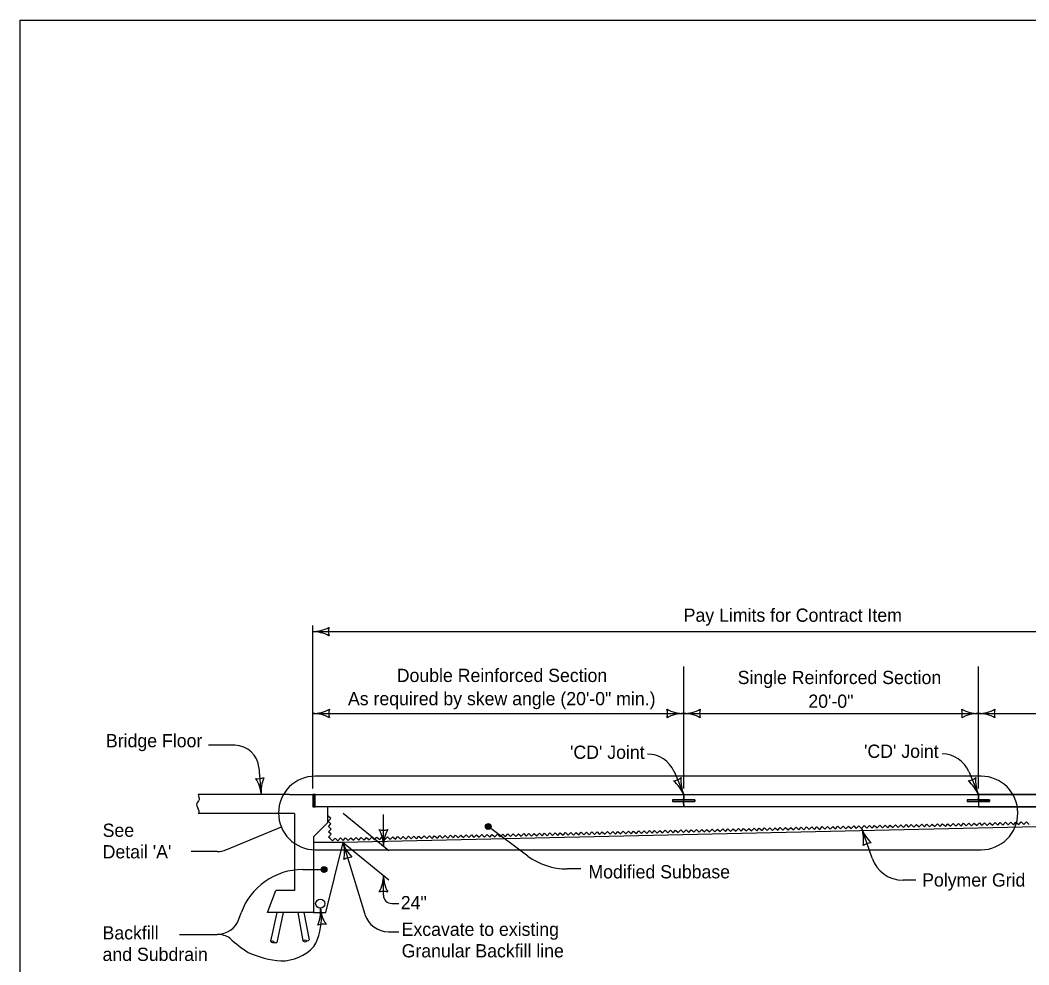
# Model space of a CAD drawing. Extents: x -2134934 to -2124557, y -2139046 to -2134021.
# Drawn here: x -2131334 to -2130115, y -2138178 to -2137036 of the extents above; entities that cross this region are included whole.
import ezdxf

# ---------------------------------------------------------------- set-up
doc = ezdxf.new("R2010")
doc.units = 0
for name, color, linetype in [('BridgeSuperStructureExisting', 7, 'Continuous'), ('dsnAlignmentStation', 7, 'Continuous'), ('dsnStdLabel', 7, 'Continuous')]:
    doc.layers.add(name, color=color, linetype=linetype)

msp = doc.modelspace()

# ---------------------------------------------------------------- linework, layer by layer
at = {"layer": 'BridgeSuperStructureExisting'}
for p, q in [((-2130980.5, -2137964.6), (-2130980.5, -2137767.6)), ((-2130980.5, -2137775), (-2129819.2, -2137775)), ((-2130532, -2137964.6), (-2130532, -2137817.1)), ((-2130175.6, -2137964.6), (-2130175.6, -2137817.1)), ((-2130980.5, -2137874), (-2130532, -2137874)), ((-2130532, -2137874), (-2130175.6, -2137874)), ((-2130175.6, -2137874), (-2129819.2, -2137874)), ((-2131074.8, -2137912.4), (-2131106.5, -2137912.4)), ((-2131045.7, -2137939.6), (-2131042.9, -2137972.1)), ((-2130172.4, -2137949.8), (-2130977.5, -2137949.8)), ((-2130543.6, -2137944.3), (-2130532, -2137972.1)), ((-2130187.2, -2137944.3), (-2130175.6, -2137972.1)), ((-2131008.7, -2137972.1), (-2131119.3, -2137972.1)), ((-2131008.7, -2137972.1), (-2130980.5, -2137972.1)), ((-2130980.5, -2137972.1), (-2130980.5, -2137986.9)), ((-2130977.5, -2137972.1), (-2130980.5, -2137972.1)), ((-2130980.5, -2137975.4), (-2130977.5, -2137972.5)), ((-2130980.5, -2137973.3), (-2130979.6, -2137972.5)), ((-2130977.5, -2137972.5), (-2130980.5, -2137972.5)), ((-2130980.5, -2137977.5), (-2130977.5, -2137974.6)), ((-2130980.5, -2137979.6), (-2130977.5, -2137976.7)), ((-2130980.5, -2137981.7), (-2130977.5, -2137978.8)), ((-2130977.5, -2137972.1), (-2129819.2, -2137972.1)), ((-2130545.4, -2137978.6), (-2130518.7, -2137978.6)), ((-2130545.4, -2137980.4), (-2130518.7, -2137980.4)), ((-2130545.4, -2137980.4), (-2130518.7, -2137980.4)), ((-2130532, -2137986.9), (-2130532, -2137972.1)), ((-2130518.7, -2137978.6), (-2130518.7, -2137980.4)), ((-2130189, -2137978.6), (-2130162.3, -2137978.6)), ((-2130189, -2137980.4), (-2130162.3, -2137980.4)), ((-2129819.2, -2137972.1), (-2130175.6, -2137972.1)), ((-2130175.6, -2137972.1), (-2130175.6, -2137978.6)), ((-2130175.6, -2137972.1), (-2130175.6, -2137986.9)), ((-2130175.6, -2137978.6), (-2130162.3, -2137978.6)), ((-2130162.3, -2137980.4), (-2130175.6, -2137980.4)), ((-2130175.6, -2137980.4), (-2130175.6, -2137986.9)), ((-2130162.3, -2137978.6), (-2130162.3, -2137980.4)), ((-2130162.3, -2137978.6), (-2130162.3, -2137980.4)), ((-2130980.5, -2137983.8), (-2130977.5, -2137980.9)), ((-2130980.5, -2137985.9), (-2130977.5, -2137983)), ((-2130980.5, -2137986.9), (-2130977.5, -2137986.9)), ((-2130979.3, -2137986.9), (-2130977.5, -2137985.1)), ((-2129819.2, -2137986.9), (-2130977.5, -2137986.9)), ((-2130962.7, -2137986.9), (-2130962.7, -2138006.2)), ((-2130175.6, -2137986.9), (-2129819.2, -2137986.9)), ((-2131002.8, -2137995), (-2131119.3, -2137995)), ((-2131002.8, -2137995), (-2131002.8, -2138087.9)), ((-2130943.9, -2137994.7), (-2130888.6, -2138039.7)), ((-2129819.2, -2138004.6), (-2130943.9, -2138030)), ((-2130895.1, -2138034.4), (-2130895.1, -2137996.2)), ((-2131018.7, -2138011.3), (-2131084.9, -2138038.7)), ((-2130962.7, -2138006.2), (-2130979.5, -2138023)), ((-2130720.3, -2138046.4), (-2130768.3, -2138010.8)), ((-2130304.1, -2138049), (-2130316.6, -2138013.1)), ((-2130979.5, -2138023), (-2130979.5, -2138114.6)), ((-2131096.2, -2138040.9), (-2131127.8, -2138040.9)), ((-2130943.9, -2138030), (-2130979.5, -2138030)), ((-2130977.5, -2138038.9), (-2130172.4, -2138038.9)), ((-2130964.6, -2138114.6), (-2130943.9, -2138030)), ((-2130943.9, -2138030), (-2130888.6, -2138075)), ((-2130917.4, -2138116.9), (-2130943.9, -2138030)), ((-2130656.2, -2138062), (-2130673.1, -2138062)), ((-2130895.1, -2138093.7), (-2130895.1, -2138069.7)), ((-2130251.3, -2138075.6), (-2130266.7, -2138075.6)), ((-2131035.4, -2138114.6), (-2131025.2, -2138087.9)), ((-2131002.8, -2138087.9), (-2131025.2, -2138087.9)), ((-2130979.5, -2138114.6), (-2131035.4, -2138114.6)), ((-2131024, -2138114.6), (-2131031.5, -2138149.4)), ((-2131016.4, -2138114.6), (-2131024.2, -2138151)), ((-2130998.7, -2138114.6), (-2130992.4, -2138149)), ((-2130991.2, -2138114.6), (-2130985.1, -2138147.6)), ((-2130979.5, -2138114.6), (-2130964.6, -2138114.6)), ((-2130885.1, -2138103.7), (-2130876.5, -2138103.7)), ((-2130889, -2138137.9), (-2130876.5, -2138137.9))]:
    msp.add_line(p, q, dxfattribs=at)
for points in [[(-2130959.7, -2138025), (-2130961.5, -2138023.4), (-2130958.4, -2138020.1), (-2130961.6, -2138017), (-2130958.5, -2138013.8), (-2130961.7, -2138010.7), (-2130958.7, -2138007.5), (-2130961.9, -2138004.4), (-2130958.8, -2138001.1), (-2130962, -2137998), (-2130961.9, -2137997.9)], [(-2130141.1, -2138007.2), (-2130139.5, -2138008.7), (-2130136.4, -2138005.5), (-2130133.2, -2138008.6), (-2130130.1, -2138005.3), (-2130126.8, -2138008.4), (-2130123.7, -2138005.2), (-2130120.5, -2138008.3), (-2130117.4, -2138005), (-2130114.2, -2138008.1)], [(-2130768, -2138007.6), (-2130769.2, -2138008.2), (-2130771, -2138008.7), (-2130771.3, -2138010.6), (-2130771.1, -2138012.2), (-2130769.9, -2138013.7), (-2130768.2, -2138013.5), (-2130766.4, -2138013.3), (-2130765.5, -2138011.8), (-2130765.3, -2138010.3), (-2130766.4, -2138008.3), (-2130767.7, -2138008.1), (-2130769.5, -2138008.6), (-2130771, -2138009.7), (-2130771, -2138011.5), (-2130769.8, -2138012.9), (-2130768.2, -2138013), (-2130766.4, -2138012.7), (-2130766.1, -2138011.6), (-2130765.7, -2138010.4), (-2130766.6, -2138008.9), (-2130767.9, -2138008.9), (-2130769.4, -2138009.2), (-2130770.5, -2138010), (-2130770, -2138011.5), (-2130768.8, -2138012.4), (-2130767.3, -2138012.5), (-2130766.9, -2138011.7), (-2130766.4, -2138010.7), (-2130767.2, -2138009.5), (-2130768.3, -2138009.2), (-2130769.3, -2138009.8), (-2130769.4, -2138010.9), (-2130768.8, -2138011.7), (-2130767.8, -2138012), (-2130767.3, -2138011.6), (-2130767, -2138010.9), (-2130767.6, -2138010), (-2130768.3, -2138009.9), (-2130769, -2138010.3), (-2130768.9, -2138010.9), (-2130768.4, -2138011.3), (-2130767.6, -2138011.3), (-2130767.7, -2138010.8), (-2130768.3, -2138010.5)], [(-2130673.2, -2138019.6), (-2130671.6, -2138021.2), (-2130668.5, -2138017.9), (-2130665.2, -2138021), (-2130662.2, -2138017.8), (-2130658.9, -2138020.9), (-2130655.8, -2138017.6), (-2130652.6, -2138020.7), (-2130649.5, -2138017.5), (-2130646.3, -2138020.6), (-2130643.2, -2138017.3), (-2130639.9, -2138020.4), (-2130636.8, -2138017.2), (-2130633.6, -2138020.3), (-2130630.5, -2138017), (-2130627.3, -2138020.1), (-2130624.2, -2138016.9), (-2130620.9, -2138020), (-2130617.8, -2138016.7), (-2130614.6, -2138019.8), (-2130611.5, -2138016.6), (-2130608.2, -2138019.7), (-2130605.1, -2138016.4), (-2130601.9, -2138019.5), (-2130598.8, -2138016.3), (-2130597.2, -2138017.8)], [(-2130597.2, -2138017.9), (-2130595.6, -2138019.4), (-2130592.5, -2138016.2), (-2130589.2, -2138019.3), (-2130586.1, -2138016), (-2130582.9, -2138019.1), (-2130579.8, -2138015.9), (-2130576.6, -2138019), (-2130573.5, -2138015.7), (-2130570.2, -2138018.8), (-2130567.1, -2138015.6), (-2130563.9, -2138018.7), (-2130560.8, -2138015.4), (-2130557.6, -2138018.5), (-2130554.5, -2138015.3), (-2130551.2, -2138018.4), (-2130548.1, -2138015.1), (-2130544.9, -2138018.2), (-2130541.8, -2138015), (-2130538.6, -2138018.1), (-2130535.5, -2138014.8), (-2130532.2, -2138017.9), (-2130529.1, -2138014.7), (-2130525.9, -2138017.8), (-2130522.8, -2138014.5), (-2130521.2, -2138016.1)], [(-2130521.2, -2138016.1), (-2130519.6, -2138017.6), (-2130516.5, -2138014.4), (-2130513.2, -2138017.4), (-2130510.1, -2138014.2), (-2130506.9, -2138017.3), (-2130503.8, -2138014.1), (-2130500.6, -2138017.2), (-2130497.5, -2138013.9), (-2130494.2, -2138017), (-2130491.1, -2138013.8), (-2130487.9, -2138016.9), (-2130484.8, -2138013.6), (-2130481.6, -2138016.7), (-2130478.5, -2138013.5), (-2130475.2, -2138016.6), (-2130472.1, -2138013.3), (-2130468.9, -2138016.4), (-2130465.8, -2138013.2), (-2130462.6, -2138016.3), (-2130459.5, -2138013), (-2130456.2, -2138016.1), (-2130453.1, -2138012.9), (-2130449.9, -2138016), (-2130446.8, -2138012.7), (-2130445.2, -2138014.3)], [(-2130445.2, -2138014.3), (-2130443.6, -2138015.8), (-2130440.5, -2138012.6), (-2130437.2, -2138015.7), (-2130434.1, -2138012.4), (-2130430.9, -2138015.5), (-2130427.8, -2138012.3), (-2130424.6, -2138015.4), (-2130421.5, -2138012.1), (-2130418.2, -2138015.2), (-2130415.1, -2138012), (-2130411.9, -2138015.1), (-2130408.8, -2138011.8), (-2130405.5, -2138014.9), (-2130402.5, -2138011.7), (-2130399.2, -2138014.8), (-2130396.1, -2138011.5), (-2130392.9, -2138014.6), (-2130389.8, -2138011.4), (-2130386.5, -2138014.5), (-2130383.5, -2138011.2), (-2130380.2, -2138014.3), (-2130377.1, -2138011.1), (-2130373.9, -2138014.2), (-2130370.8, -2138010.9), (-2130369.2, -2138012.5)], [(-2130369.2, -2138012.5), (-2130367.5, -2138014.1), (-2130364.4, -2138010.8), (-2130361.2, -2138013.9), (-2130358.1, -2138010.7), (-2130354.9, -2138013.8), (-2130351.8, -2138010.5), (-2130348.5, -2138013.6), (-2130345.4, -2138010.4), (-2130342.2, -2138013.5), (-2130339.1, -2138010.2), (-2130335.9, -2138013.3), (-2130332.8, -2138010.1), (-2130329.5, -2138013.2), (-2130326.4, -2138009.9), (-2130323.2, -2138013), (-2130320.1, -2138009.8), (-2130316.9, -2138012.9), (-2130313.8, -2138009.6), (-2130310.5, -2138012.7), (-2130307.4, -2138009.5), (-2130304.2, -2138012.6), (-2130301.1, -2138009.3), (-2130297.9, -2138012.4), (-2130294.8, -2138009.2), (-2130293.2, -2138010.7)], [(-2130293.2, -2138010.7), (-2130291.5, -2138012.3), (-2130288.4, -2138009), (-2130285.2, -2138012.1), (-2130282.1, -2138008.9), (-2130278.9, -2138012), (-2130275.8, -2138008.7), (-2130272.5, -2138011.8), (-2130269.4, -2138008.6), (-2130266.2, -2138011.7), (-2130263.1, -2138008.4), (-2130259.9, -2138011.5), (-2130256.8, -2138008.3), (-2130253.5, -2138011.4), (-2130250.4, -2138008.1), (-2130247.2, -2138011.2), (-2130244.1, -2138008), (-2130240.9, -2138011.1), (-2130237.8, -2138007.8), (-2130234.5, -2138010.9), (-2130231.4, -2138007.7), (-2130228.2, -2138010.8), (-2130225.1, -2138007.6), (-2130221.9, -2138010.7), (-2130218.8, -2138007.4), (-2130217.1, -2138009)], [(-2130217.1, -2138009), (-2130215.5, -2138010.5), (-2130212.4, -2138007.3), (-2130209.2, -2138010.4), (-2130206.1, -2138007.1), (-2130202.9, -2138010.2), (-2130199.8, -2138007), (-2130196.5, -2138010.1), (-2130193.4, -2138006.8), (-2130190.2, -2138009.9), (-2130187.1, -2138006.7), (-2130183.8, -2138009.8), (-2130180.8, -2138006.5), (-2130177.5, -2138009.6), (-2130174.4, -2138006.4), (-2130171.2, -2138009.5), (-2130168.1, -2138006.2), (-2130164.8, -2138009.3), (-2130161.8, -2138006.1), (-2130158.5, -2138009.2), (-2130155.4, -2138005.9), (-2130152.2, -2138009), (-2130149.1, -2138005.8), (-2130145.8, -2138008.9), (-2130142.8, -2138005.6), (-2130141.1, -2138007.2)], [(-2130959.9, -2138024.9), (-2130959.9, -2138024.8), (-2130956.6, -2138027.9), (-2130953.5, -2138024.7), (-2130950.3, -2138027.8), (-2130947.2, -2138024.5), (-2130944, -2138027.6), (-2130940.9, -2138024.4), (-2130937.6, -2138027.5), (-2130934.5, -2138024.2), (-2130931.3, -2138027.3), (-2130928.2, -2138024.1), (-2130925, -2138027.2), (-2130921.9, -2138023.9), (-2130918.6, -2138027), (-2130915.5, -2138023.8), (-2130912.3, -2138026.9), (-2130909.2, -2138023.6), (-2130906, -2138026.7), (-2130902.9, -2138023.5), (-2130901.2, -2138025)], [(-2130901.2, -2138025), (-2130899.6, -2138026.5), (-2130896.5, -2138023.3), (-2130893.3, -2138026.4), (-2130890.2, -2138023.1), (-2130886.9, -2138026.2), (-2130883.9, -2138023), (-2130880.6, -2138026.1), (-2130877.5, -2138022.8), (-2130874.3, -2138025.9), (-2130871.2, -2138022.7), (-2130867.9, -2138025.8), (-2130864.9, -2138022.5), (-2130861.6, -2138025.6), (-2130858.5, -2138022.4), (-2130855.3, -2138025.5), (-2130852.2, -2138022.2), (-2130848.9, -2138025.3), (-2130845.8, -2138022.1), (-2130842.6, -2138025.2), (-2130839.5, -2138021.9), (-2130836.3, -2138025), (-2130833.2, -2138021.8), (-2130829.9, -2138024.9), (-2130826.8, -2138021.6), (-2130825.2, -2138023.2)], [(-2130825.2, -2138023.2), (-2130823.6, -2138024.7), (-2130820.5, -2138021.5), (-2130817.3, -2138024.6), (-2130814.2, -2138021.3), (-2130810.9, -2138024.4), (-2130807.8, -2138021.2), (-2130804.6, -2138024.3), (-2130801.5, -2138021), (-2130798.3, -2138024.1), (-2130795.2, -2138020.9), (-2130791.9, -2138024), (-2130788.8, -2138020.7), (-2130785.6, -2138023.8), (-2130782.5, -2138020.6), (-2130779.3, -2138023.7), (-2130776.2, -2138020.5), (-2130772.9, -2138023.5), (-2130769.8, -2138020.3), (-2130766.6, -2138023.4), (-2130763.5, -2138020.2), (-2130760.3, -2138023.2), (-2130757.2, -2138020), (-2130753.9, -2138023.1), (-2130750.8, -2138019.9), (-2130749.2, -2138021.4)], [(-2130749.2, -2138021.4), (-2130747.6, -2138022.9), (-2130744.5, -2138019.7), (-2130741.3, -2138022.8), (-2130738.2, -2138019.6), (-2130734.9, -2138022.6), (-2130731.8, -2138019.4), (-2130728.6, -2138022.5), (-2130725.5, -2138019.3), (-2130722.3, -2138022.3), (-2130719.2, -2138019.1), (-2130715.9, -2138022.2), (-2130712.8, -2138019), (-2130709.6, -2138022.1), (-2130706.5, -2138018.8), (-2130703.3, -2138021.9), (-2130700.2, -2138018.7), (-2130696.9, -2138021.8), (-2130693.8, -2138018.5), (-2130690.6, -2138021.6), (-2130687.5, -2138018.4), (-2130684.3, -2138021.5), (-2130681.2, -2138018.2), (-2130677.9, -2138021.3), (-2130674.8, -2138018.1), (-2130673.2, -2138019.6)], [(-2130967.2, -2138065.9), (-2130966, -2138065.3), (-2130964.2, -2138064.8), (-2130963.9, -2138062.9), (-2130964.1, -2138061.3), (-2130965.3, -2138059.8), (-2130967, -2138060), (-2130968.8, -2138060.2), (-2130969.7, -2138061.7), (-2130969.9, -2138063.2), (-2130968.8, -2138065.2), (-2130967.5, -2138065.4), (-2130965.6, -2138064.9), (-2130964.1, -2138063.8), (-2130964.2, -2138062), (-2130965.4, -2138060.6), (-2130967, -2138060.5), (-2130968.8, -2138060.8), (-2130969.1, -2138061.9), (-2130969.5, -2138063.1), (-2130968.6, -2138064.6), (-2130967.3, -2138064.6), (-2130965.8, -2138064.3), (-2130964.7, -2138063.5), (-2130965.2, -2138062), (-2130966.4, -2138061.1), (-2130967.9, -2138061), (-2130968.3, -2138061.8), (-2130968.8, -2138062.8), (-2130968, -2138064), (-2130966.9, -2138064.2), (-2130965.9, -2138063.7), (-2130965.8, -2138062.6), (-2130966.3, -2138061.8), (-2130967.4, -2138061.5), (-2130967.9, -2138061.9), (-2130968.2, -2138062.5), (-2130967.6, -2138063.4), (-2130966.9, -2138063.6), (-2130966.2, -2138063.2), (-2130966.3, -2138062.6), (-2130966.8, -2138062.2), (-2130967.6, -2138062.2), (-2130967.5, -2138062.7), (-2130966.9, -2138063)]]:
    msp.add_lwpolyline(points, dxfattribs=at)
for centre, radius in [((-2130768.3, -2138010.8), 3.46), ((-2130966.9, -2138062.7), 3.46), ((-2130971.5, -2138103.9), 5.57)]:
    msp.add_circle(centre, radius, dxfattribs=at)
for centre, radius, start, end in [((-2130981.1, -2137732.3), 42.7, 270, 298.0725), ((-2130945.2, -2137775), 16.5, 162.2666, 197.7334), ((-2130981.1, -2137817.8), 42.7, 61.9275, 90), ((-2130980.5, -2137831.3), 42.7, 270, 298.0725), ((-2130944.7, -2137874), 16.5, 162.2666, 197.7334), ((-2130567.9, -2137874), 16.5, 342.2666, 17.7333), ((-2130532, -2137831.3), 42.7, 241.9275, 270), ((-2130532, -2137831.3), 42.7, 270, 298.0725), ((-2130496.2, -2137874), 16.5, 162.2666, 197.7334), ((-2130211.5, -2137874), 16.5, 342.2666, 17.7333), ((-2130175.6, -2137831.3), 42.7, 241.9275, 270), ((-2130175.6, -2137831.3), 42.7, 270, 298.0725), ((-2130139.8, -2137874), 16.5, 162.2666, 197.7334), ((-2130980.5, -2137916.8), 42.7, 61.9275, 90), ((-2130532, -2137916.8), 42.7, 90, 118.0725), ((-2130532, -2137916.8), 42.7, 61.9275, 90), ((-2130175.6, -2137916.8), 42.7, 90, 118.0725), ((-2130175.6, -2137916.8), 42.7, 61.9275, 90), ((-2131075.3, -2137942.1), 29.7, 4.9696, 89.1065), ((-2130575.6, -2137957.7), 34.6, 22.5907, 90), ((-2130219.2, -2137957.6), 34.6, 22.5907, 90), ((-2131046, -2137936.4), 16.5, 257.2356, 292.7023), ((-2131085.4, -2137975.8), 42.7, 4.969, 33.0415), ((-2131000.3, -2137968.4), 42.7, 156.8965, 184.969), ((-2130977.5, -2137994.3), 44.5, 90, 269.9998), ((-2130545.8, -2137939), 16.5, 274.8595, 310.3262), ((-2130571.5, -2137988.5), 42.7, 22.5928, 50.6653), ((-2130492.6, -2137955.6), 42.7, 174.5203, 202.5928), ((-2130189.4, -2137939), 16.5, 274.8572, 310.3239), ((-2130215.1, -2137988.5), 42.7, 22.5905, 50.663), ((-2130136.2, -2137955.6), 42.7, 174.5181, 202.5905), ((-2130172.4, -2137994.3), 44.5, 270.0002, 90), ((-2130895.1, -2137998.6), 16.5, 252.2666, 287.7333), ((-2130937.8, -2138034.4), 42.7, 360, 28.0725), ((-2130852.3, -2138034.4), 42.7, 151.9275, 180), ((-2130276.2, -2137999), 42.7, 199.1779, 227.2504), ((-2130357, -2138027.1), 42.7, 351.1054, 19.1779), ((-2131096.2, -2138011.2), 29.7, 270, 292.4496), ((-2130903, -2138017.5), 42.7, 196.9537, 225.0262), ((-2130984.8, -2138042.4), 42.7, 348.8812, 16.9537), ((-2130903, -2138017.5), 42.7, 196.9537, 225.0262), ((-2130984.8, -2138042.4), 42.7, 348.8812, 16.9537), ((-2130304.8, -2138046.9), 16.5, 91.4446, 126.9113), ((-2130933.4, -2138064.3), 16.5, 89.2203, 124.687), ((-2130933.4, -2138064.3), 16.5, 89.2203, 124.687), ((-2130673.1, -2137982.8), 79.2, 233.4243, 270), ((-2130266.7, -2138036), 39.6, 199.1769, 270), ((-2130992.7, -2138141.9), 79.2, 90, 160.3012), ((-2130937.8, -2138069.7), 42.7, 331.9275, 360), ((-2130852.3, -2138069.7), 42.7, 180, 208.0725), ((-2130895.1, -2138105.6), 16.5, 72.2666, 107.7334), ((-2130885.1, -2138093.7), 10, 180, 270), ((-2131013.6, -2138113.4), 42.5, 337.1139, 5.1864), ((-2130929, -2138105.7), 42.5, 185.1864, 213.2589), ((-2131096.1, -2138113.4), 27.7, 270, 340.3019), ((-2130889, -2138108.2), 29.7, 196.9535, 270), ((-2130968.1, -2138145), 16.4, 77.453, 112.9197), ((-2131096.1, -2138168.8), 27.7, 56.8248, 90)]:
    msp.add_arc(centre, radius, start, end, dxfattribs=at)
for points in [[(-2131119.3, -2137972.1), (-2131118.1, -2137978), (-2131121.1, -2137984), (-2131118.4, -2137991.7), (-2131118.8, -2137995)], [(-2131031.5, -2138149.4), (-2131028.4, -2138149.1), (-2131026.6, -2138150.8), (-2131024.2, -2138151)], [(-2131031.5, -2138149.4), (-2131029.4, -2138150.9), (-2131027, -2138150.7)], [(-2130992.4, -2138149), (-2130989.6, -2138147.8), (-2130986.8, -2138149), (-2130985.1, -2138147.6)], [(-2130992.4, -2138149), (-2130989.7, -2138149.9), (-2130987.6, -2138149)]]:
    msp.add_spline(points, degree=3, dxfattribs=at)
at = {"layer": 'dsnAlignmentStation'}
msp.add_lwpolyline([(-2131334.4, -2137035.9), (-2128199.4, -2137035.9), (-2128199.4, -2139045.9), (-2131334.4, -2139045.9)], close=True, dxfattribs=at)
at = {"layer": 'dsnStdLabel'}
for p, q in [((-2130977.5, -2137986.9), (-2130977.5, -2137972.1)), ((-2130977.5, -2137972.1), (-2130532, -2137972.1)), ((-2130977.5, -2137986.9), (-2130977.5, -2137972.1)), ((-2130532, -2137978.5), (-2130545.4, -2137978.6)), ((-2130545.4, -2137978.6), (-2130532, -2137978.5)), ((-2130545.4, -2137978.6), (-2130545.4, -2137980.4)), ((-2130545.4, -2137978.6), (-2130545.4, -2137980.4)), ((-2130545.4, -2137978.6), (-2130545.4, -2137980.4)), ((-2130518.7, -2137978.6), (-2130545.4, -2137978.6)), ((-2130545.4, -2137980.4), (-2130532.1, -2137980.4)), ((-2130532.1, -2137980.4), (-2130532, -2137986.9)), ((-2130532, -2137986.9), (-2130532.1, -2137980.4)), ((-2130532, -2137972.1), (-2130532, -2137978.5)), ((-2130532, -2137978.5), (-2130532, -2137972.1)), ((-2130532, -2137978.5), (-2130532, -2137972.1)), ((-2130532, -2137972.1), (-2130175.6, -2137972.1)), ((-2130518.7, -2137978.6), (-2130532, -2137978.5)), ((-2130518.7, -2137978.6), (-2130532, -2137978.6)), ((-2130532, -2137986.9), (-2130532, -2137980.4)), ((-2130532, -2137980.4), (-2130518.7, -2137980.4)), ((-2130518.7, -2137980.4), (-2130518.7, -2137978.6)), ((-2130518.7, -2137980.4), (-2130518.7, -2137978.6)), ((-2130189, -2137978.6), (-2130189, -2137980.4)), ((-2130175.6, -2137978.6), (-2130189, -2137978.6)), ((-2130189, -2137978.6), (-2130189, -2137980.4)), ((-2130189, -2137980.4), (-2130175.6, -2137980.4)), ((-2130175.6, -2137978.6), (-2130175.6, -2137972.1)), ((-2130175.6, -2137972.1), (-2130175.6, -2137978.6)), ((-2130162.3, -2137978.6), (-2130175.6, -2137978.6)), ((-2130175.6, -2137980.4), (-2130175.6, -2137986.9)), ((-2130962.2, -2137986.9), (-2130977.5, -2137986.9)), ((-2130940.4, -2137986.9), (-2130962.2, -2137986.9)), ((-2130532, -2137986.9), (-2130940.4, -2137986.9)), ((-2130175.6, -2137986.9), (-2130532, -2137986.9)), ((-2130992.7, -2138062.7), (-2130966.9, -2138062.7)), ((-2131070, -2138122.7), (-2131067.3, -2138115.2)), ((-2131141.8, -2138141.1), (-2131096.1, -2138141.1))]:
    msp.add_line(p, q, dxfattribs=at)
for centre, radius, start, end in [((-2131041.3, -2138120.8), 71.3, 330.5092, 2.0511), ((-2130969.6, -2138025.7), 163.6, 227.1442, 236.9942), ((-2131009.8, -2138055), 118.5, 245.5915, 265.546), ((-2131019.3, -2138118.2), 55, 270.3325, 316.7198)]:
    msp.add_arc(centre, radius, start, end, dxfattribs=at)

# ---------------------------------------------------------------- texts
for s, p in [('Pay Limits for Contract Item', (-2130532, -2137763.2)), ('Double Reinforced Section', (-2130879, -2137836)), ('Single Reinforced Section', (-2130466.7, -2137838.5)), ('As required by skew angle (20\'-0" min.)', (-2130938, -2137864.1)), ('20\'-0"', (-2130381.2, -2137867.2)), ('Bridge Floor', (-2131230.7, -2137914.9)), ("'CD' Joint", (-2130669.4, -2137928.9)), ("'CD' Joint", (-2130313.8, -2137927.7)), ('See', (-2131234.7, -2138023.2)), ("Detail 'A'", (-2131234.7, -2138049.2)), ('Modified Subbase', (-2130647.2, -2138073.4)), ('Polymer Grid', (-2130243.6, -2138083.3)), ('24"', (-2130874.1, -2138110.7)), ('Excavate to existing', (-2130873.1, -2138142.9)), ('Backfill', (-2131234.8, -2138147.2)), ('and Subdrain', (-2131234.8, -2138173.2)), ('Granular Backfill line', (-2130873.1, -2138168.9))]:
    msp.add_text(s, height=16, dxfattribs=at).set_placement(p)

doc.saveas('drawing.dxf')
